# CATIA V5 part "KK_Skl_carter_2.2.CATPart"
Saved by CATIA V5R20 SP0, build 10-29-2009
Part number: Skl_carter_2.2
Publications: "Droite.4", "Axe_pivot_carter2.2_carter_manche", "Plan.Ref5", "Point.2", "Point.3", "Plan_Ref1", "Axe_pivot_galet1", "Axe_pivot_galet4", "Axe_pivot_galet3", "Axe_pivot_galet2", "Point.4", "Point.5", "Point.6", "Point.7"
Bounding box of the stored display mesh (mm): x -7.5 to 32.5, y 100 to 335, z -15 to 15
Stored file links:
  G:\Khaled_CFAO_2011\ST2M\ST2M_GR2\aandujar\Khaled\CAD_thinkMOTION\KK_Skl_carter_2.2.CATPart
  G:\Khaled_CFAO_2011\ST2M\ST2M_GR2\aandujar\Khaled\CAD_thinkMOTION\KK_Skl_scie_mecanique.CATProduct
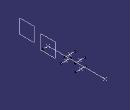
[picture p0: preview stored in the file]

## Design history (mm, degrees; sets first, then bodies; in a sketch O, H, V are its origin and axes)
WSupportSet1: ActiveGrid {3dwsupport RefPoint {point stored without definition}, 3DWOS ({wsupport Support xy-plane, RefPoint {3dwsupport}, GridIn {cartgrid Value 100, Stepbid1 0, Value 100, Stepbid2 0, Direction (1, 0, 0)}, GeometricData ({line type PtDir, Direction (1, 0, 0), Support xy-plane}; {line type PtDir, Direction (0, 1, 0), Support yz-plane})}; {wsupport Support yz-plane, RefPoint {3dwsupport}, GridIn {cartgrid Value 100, Stepbid1 0, Value 100, Stepbid2 0, Direction (0, 1, 0)}, GeometricData ({line type PtDir, Direction (0, 1, 0), Support yz-plane}; {line type PtDir, Direction (0, 0, 1), Support zx-plane})}; {wsupport Support zx-plane, RefPoint {3dwsupport}, GridIn {cartgrid Value 100, Stepbid1 0, Value 100, Stepbid2 0, Direction (0, 0, 1)}, GeometricData ({line type PtDir, Direction (0, 0, 1), Support zx-plane}; {line type PtDir, Direction (1, 0, 0), Support xy-plane})}), GeometricData ({line type PtDir, RefPoint {point stored without definition}, Direction (1, 0, 0), Support xy-plane}; {line type PtDir, RefPoint {point stored without definition}, Direction (0, 1, 0), Support yz-plane}; {line type PtDir, RefPoint {point stored without definition}, Direction (0, 0, 1), Support zx-plane})}
Set1
  Line1: type PtPt, FirstPoint Point1, SecondPoint Point2, Support Plane1
  Line2 "Axe_pivot_carter2.2_carter_manche": type Normal, RefPoint Point2, RefSkin Plane2, Start 0, End 20
  Line3 "Axe_pivot_galet1": type Normal, RefPoint Point3, RefSkin Plane2, Start -20, End 20
  Line4 "Axe_pivot_galet4": type Normal, RefPoint Point4, RefSkin Plane2, Start -20, End 20
  Line5 "Axe_pivot_galet3": type Normal, RefPoint Point5, RefSkin Plane2, Start -20, End 20
  Line6 "Axe_pivot_galet2": type Normal, RefPoint Point6, RefSkin Plane2, Start -20, End 20
Set2
  Plane1 "Plan.Ref5": linked copy from another document
  Point1: linked copy from another document
  Point2: linked copy from another document
  Plane2 "Plan_Ref1": linked copy from another document
  Point3 to Point6: linked copy from another document
Body1 (main body)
